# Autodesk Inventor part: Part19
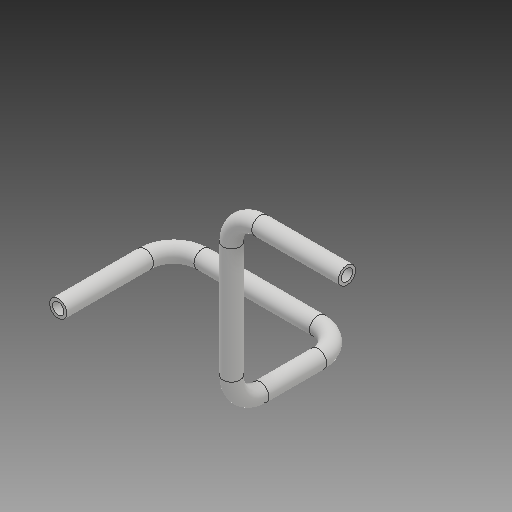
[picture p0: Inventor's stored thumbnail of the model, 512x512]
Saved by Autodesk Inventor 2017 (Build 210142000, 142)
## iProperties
Created: 2015-05
Part Number: Part19
Material: Generic
Document SubType Name: Modeling
Designer: Sandeep
Density: 1 g/cm^3
Appearance: Default
Author: Sandeep
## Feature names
1. Sweep1
## Parameters: d10 = 6 mm, d11 = 4 mm, d12 = 0, d13 = 0
